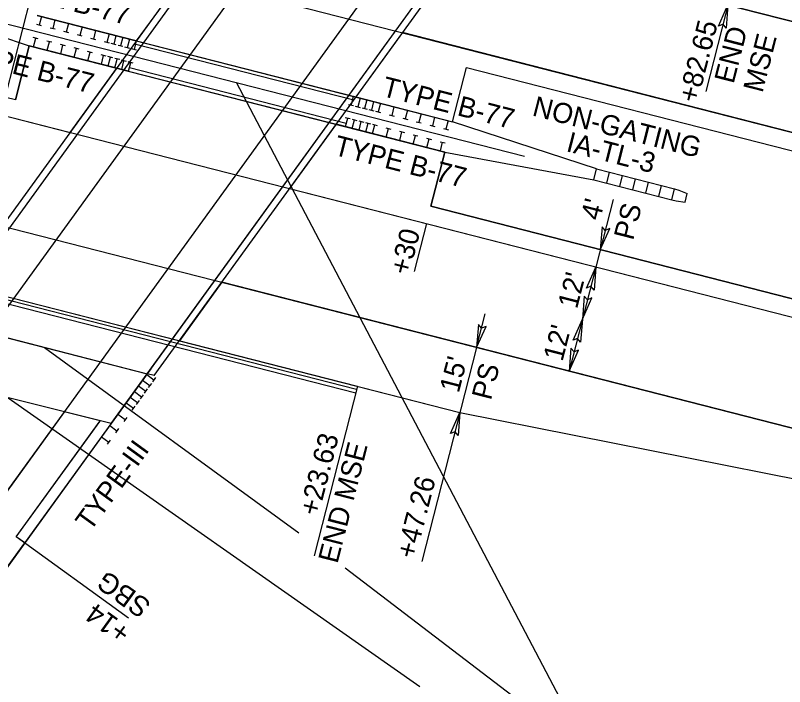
# Model space of a CAD drawing. Extents: x 1183930 to 1185370, y 573068 to 574871.
# Drawn here: x 1184495.2 to 1184666.9, y 573937.3 to 574087.2 of the extents above; entities that cross this region are included whole.
import ezdxf

# ---------------------------------------------------------------- set-up
doc = ezdxf.new("R2010")
doc.units = 0
for name, color, linetype in [('E_NCDOT_Terrain_Model_Flow_Arrows', 7, 'Continuous'), ('E_NCDOT_Terrain_Model_Spot_Elevation', 7, 'Continuous'), ('E_NCDOT_Terrain_Model_Triangles', 7, 'Continuous'), ('E_NCDOT_Vertical_Profile_Ground_Line', 7, 'Continuous'), ('P_NCDOT_Horizontal_Alignment', 7, 'Continuous'), ('P_NCDOT_Horizontal_Alignment_Curve_and_Spiral_Data', 7, 'Continuous'), ('P_NCDOT_Horizontal_Alignment_Direction_Label', 7, 'Continuous'), ('P_NCDOT_Horizontal_Alignment_Station_Label', 7, 'Continuous'), ('P_NCDOT_Horizontal_Alignment_Tick_Large', 7, 'Continuous'), ('P_NCDOT_Vertical_Profile_Grade', 7, 'Continuous'), ('P_RDY_Profile_Special_Ditch_L', 7, 'Continuous'), ('P_SMU_D_Unit_Label', 7, 'Continuous'), ('P_SMU_Deck', 7, 'Continuous'), ('PC_OBJECT', 7, 'Continuous'), ('PC_PADFOOTING', 7, 'Continuous'), ('PS_HATCH', 7, 'Continuous')]:
    doc.layers.add(name, color=color, linetype=linetype)

msp = doc.modelspace()

# ---------------------------------------------------------------- linework, layer by layer
for points in [[(1184652.15, 574084.85), (1184654.25, 574089.54), (1184653.86, 574084.38), (1184653.15, 574085.23)], [(1184626.14, 574040.02), (1184625.73, 574034.9), (1184627.87, 574039.61), (1184626.83, 574039.21)], [(1184622.64, 574026.34), (1184624.74, 574031.03), (1184624.35, 574025.87), (1184623.64, 574026.72)], [(1184622.18, 574024.52), (1184621.76, 574019.4), (1184623.9, 574024.11), (1184622.87, 574023.71)], [(1184619.66, 574014.72), (1184621.76, 574019.4), (1184621.37, 574014.25), (1184620.66, 574015.1)], [(1184598.55, 574018.19), (1184598.14, 574013.07), (1184600.28, 574017.77), (1184599.24, 574017.37)], [(1184619.2, 574012.9), (1184618.79, 574007.78), (1184620.92, 574012.49), (1184619.89, 574012.08)], [(1184592.32, 573993.85), (1184594.42, 573998.53), (1184594.03, 573993.38), (1184593.32, 573994.23)]]:
    msp.add_lwpolyline(points, close=True)
at = {"layer": 'E_NCDOT_Terrain_Model_Flow_Arrows'}
msp.add_line((1184432.84, 574038.35), (1184571.16, 574002.94), dxfattribs=at)
at = {"layer": 'E_NCDOT_Terrain_Model_Spot_Elevation'}
for p, q in [((1184522.09, 574080.79), (1184570.41, 574068.42)), ((1184569.05, 574063.09), (1184520.61, 574075.49)), ((1184571.34, 574003.67), (1184433.02, 574039.08))]:
    msp.add_line(p, q, dxfattribs=at)
at = {"layer": 'E_NCDOT_Terrain_Model_Triangles'}
for q in [(1184514.11, 573996.68), (1184514.01, 573996.54)]:
    msp.add_line((1184495.37, 573970.79), q, dxfattribs=at)
at = {"layer": 'E_NCDOT_Vertical_Profile_Ground_Line'}
for p, q in [((1184449.47, 573978.44), (1184665.23, 574276.54)), ((1184449.47, 573978.44), (1184665.23, 574276.54)), ((1184413.69, 573853.97), (1184639.53, 574165.99)), ((1184413.69, 573853.97), (1184639.53, 574165.99)), ((1184500, 574087.22), (1184592.76, 574063.47)), ((1184500, 574087.22), (1184592.76, 574063.47)), ((1184500, 574087.22), (1184592.76, 574063.47)), ((1184495.16, 574068.33), (1184498.26, 574080.44)), ((1184495.16, 574068.33), (1184498.26, 574080.44)), ((1184498.26, 574080.44), (1184591.02, 574056.69)), ((1184498.26, 574080.44), (1184591.02, 574056.69)), ((1184498.26, 574080.44), (1184591.02, 574056.69)), ((1184592.76, 574063.47), (1184595.86, 574075.58)), ((1184592.76, 574063.47), (1184595.86, 574075.58)), ((1184595.86, 574075.58), (1184964.43, 573981.23)), ((1184595.86, 574075.58), (1184964.43, 573981.23)), ((1184595.86, 574075.58), (1184970.78, 573979.6)), ((1184591.02, 574056.69), (1184587.92, 574044.58)), ((1184591.02, 574056.69), (1184587.92, 574044.58)), ((1184412.83, 574045.02), (1184569.95, 574004.8)), ((1184412.83, 574045.02), (1184594.42, 573998.53)), ((1184587.92, 574044.58), (1184956.49, 573950.23)), ((1184587.92, 574044.58), (1184956.49, 573950.23)), ((1184587.92, 574044.58), (1184962.85, 573948.6)), ((1184594.42, 573998.53), (1184790.9, 573959.59))]:
    msp.add_line(p, q, dxfattribs=at)
at = {"layer": 'P_NCDOT_Horizontal_Alignment'}
for p, q in [((1184397.22, 573889.19), (1184673.34, 574270.68)), ((1184405.59, 573859.83), (1184695.92, 574260.95)), ((1184143.08, 574220.4), (1184971.37, 574008.35)), ((1184143.08, 574220.4), (1184977.73, 574006.73)), ((1184137.13, 574197.15), (1184965.42, 573985.1)), ((1184137.13, 574197.15), (1184971.78, 573983.48)), ((1184127.21, 574158.4), (1184955.5, 573946.35)), ((1184127.21, 574158.4), (1184961.86, 573944.73)), ((1184121.26, 574135.15), (1184949.55, 573923.1)), ((1184121.26, 574135.15), (1184955.9, 573921.48))]:
    msp.add_line(p, q, dxfattribs=at)
at = {"layer": 'P_NCDOT_Horizontal_Alignment_Curve_and_Spiral_Data'}
for p, q in [((1184522.23, 574081.53), (1184570.6, 574069.15)), ((1184520.42, 574074.77), (1184568.86, 574062.37)), ((1184433.21, 574039.8), (1184571.53, 574004.39))]:
    msp.add_line(p, q, dxfattribs=at)
at = {"layer": 'P_NCDOT_Horizontal_Alignment_Direction_Label'}
for p, q in [((1184477.22, 574019.34), (1184562.83, 574137.61)), ((1184478.79, 574018.94), (1184564.39, 574137.21)), ((1184524.61, 574007.21), (1184610.21, 574125.48)), ((1184526.17, 574006.81), (1184611.78, 574125.08)), ((1184526.17, 574006.81), (1184524.61, 574007.21))]:
    msp.add_line(p, q, dxfattribs=at)
at = {"layer": 'P_NCDOT_Horizontal_Alignment_Station_Label'}
for p in [(1184478.79, 574018.94), (1184516.45, 573995.93), (1184516.55, 573996.08)]:
    msp.add_line(p, (1184524.61, 574007.21), dxfattribs=at)
msp.add_lwpolyline([(1184516.55, 573996.08), (1184470.52, 574007.53), (1184478.79, 574018.94), (1184524.61, 574007.21)], close=True, dxfattribs=at)
at = {"layer": 'P_NCDOT_Horizontal_Alignment_Tick_Large'}
for p, q in [((1184466.13, 574090.99), (1184498.26, 574080.44)), ((1184624.9, 574052.93), (1184592.76, 574063.47)), ((1184591.02, 574056.69), (1184624.28, 574050.5)), ((1184514.4, 573993.1), (1184413.69, 573853.97))]:
    msp.add_line(p, q, dxfattribs=at)
at = {"layer": 'P_NCDOT_Vertical_Profile_Grade'}
for p, q in [((1184522.16, 574081.55), (1184500, 574087.22)), ((1184500.97, 574086.97), (1184500.47, 574085.04)), ((1184504, 574086.2), (1184503.5, 574084.26)), ((1184501.03, 574084.89), (1184499.92, 574085.18)), ((1184504.05, 574084.12), (1184502.95, 574084.4)), ((1184507.02, 574085.42), (1184506.53, 574083.49)), ((1184510.05, 574084.65), (1184509.55, 574082.71)), ((1184513.08, 574083.87), (1184512.58, 574081.94)), ((1184500.28, 574081.99), (1184499.17, 574082.27)), ((1184499.23, 574080.19), (1184499.73, 574082.13)), ((1184507.08, 574083.34), (1184505.97, 574083.63)), ((1184510.11, 574082.57), (1184509, 574082.85)), ((1184513.14, 574081.79), (1184512.03, 574082.08)), ((1184516.11, 574083.1), (1184515.61, 574081.16)), ((1184517.62, 574082.71), (1184517.12, 574080.77)), ((1184519.13, 574082.32), (1184518.64, 574080.39)), ((1184520.42, 574074.77), (1184498.26, 574080.44)), ((1184503.31, 574081.21), (1184502.2, 574081.5)), ((1184502.26, 574079.42), (1184502.76, 574081.35)), ((1184506.34, 574080.44), (1184505.23, 574080.72)), ((1184505.29, 574078.64), (1184505.78, 574080.58)), ((1184516.16, 574081.02), (1184515.05, 574081.3)), ((1184517.68, 574080.63), (1184516.57, 574080.92)), ((1184519.19, 574080.24), (1184518.08, 574080.53)), ((1184520.65, 574081.94), (1184520.15, 574080)), ((1184522.16, 574081.55), (1184521.66, 574079.61)), ((1184509.37, 574079.66), (1184508.26, 574079.95)), ((1184508.31, 574077.87), (1184508.81, 574079.8)), ((1184512.39, 574078.89), (1184511.28, 574079.17)), ((1184511.34, 574077.09), (1184511.84, 574079.03)), ((1184520.71, 574079.86), (1184519.6, 574080.14)), ((1184522.22, 574079.47), (1184521.11, 574079.75)), ((1184515.42, 574078.11), (1184514.31, 574078.4)), ((1184514.37, 574076.32), (1184514.87, 574078.25)), ((1184516.93, 574077.72), (1184515.82, 574078.01)), ((1184515.88, 574075.93), (1184516.38, 574077.87)), ((1184518.45, 574077.34), (1184517.34, 574077.62)), ((1184517.4, 574075.54), (1184517.89, 574077.48)), ((1184519.96, 574076.95), (1184518.85, 574077.23)), ((1184518.91, 574075.15), (1184519.41, 574077.09)), ((1184521.48, 574076.56), (1184520.37, 574076.85)), ((1184520.42, 574074.77), (1184520.92, 574076.7)), ((1184570.6, 574069.15), (1184570.1, 574067.21)), ((1184570.6, 574069.15), (1184592.76, 574063.47)), ((1184572.11, 574068.76), (1184571.62, 574066.82)), ((1184573.63, 574068.37), (1184573.13, 574066.44)), ((1184569.55, 574067.35), (1184570.66, 574067.07)), ((1184571.06, 574066.97), (1184572.17, 574066.68)), ((1184572.57, 574066.58), (1184573.68, 574066.29)), ((1184575.14, 574067.99), (1184574.64, 574066.05)), ((1184576.65, 574067.6), (1184576.16, 574065.66)), ((1184579.68, 574066.82), (1184579.18, 574064.89)), ((1184574.09, 574066.19), (1184575.2, 574065.91)), ((1184575.6, 574065.8), (1184576.71, 574065.52)), ((1184578.63, 574065.03), (1184579.74, 574064.74)), ((1184582.71, 574066.05), (1184582.21, 574064.11)), ((1184585.73, 574065.27), (1184585.24, 574063.34)), ((1184568.8, 574064.45), (1184569.91, 574064.16)), ((1184568.86, 574062.37), (1184569.36, 574064.3)), ((1184570.32, 574064.06), (1184571.43, 574063.77)), ((1184570.38, 574061.98), (1184570.87, 574063.92)), ((1184571.83, 574063.67), (1184572.94, 574063.39)), ((1184571.89, 574061.59), (1184572.39, 574063.53)), ((1184573.34, 574063.28), (1184574.45, 574063)), ((1184573.4, 574061.2), (1184573.9, 574063.14)), ((1184581.66, 574064.25), (1184582.77, 574063.97)), ((1184584.68, 574063.48), (1184585.79, 574063.19)), ((1184588.76, 574064.5), (1184588.27, 574062.56)), ((1184591.79, 574063.72), (1184591.29, 574061.79)), ((1184568.86, 574062.37), (1184591.02, 574056.69)), ((1184574.86, 574062.9), (1184575.97, 574062.61)), ((1184574.92, 574060.82), (1184575.41, 574062.75)), ((1184577.89, 574062.12), (1184579, 574061.84)), ((1184577.94, 574060.04), (1184578.44, 574061.98)), ((1184587.71, 574062.7), (1184588.82, 574062.42)), ((1184590.74, 574061.93), (1184591.85, 574061.64)), ((1184580.91, 574061.35), (1184582.02, 574061.06)), ((1184580.97, 574059.27), (1184581.47, 574061.2)), ((1184583.94, 574060.57), (1184585.05, 574060.29)), ((1184584, 574058.49), (1184584.49, 574060.43)), ((1184586.97, 574059.8), (1184588.08, 574059.51)), ((1184587.03, 574057.72), (1184587.52, 574059.65)), ((1184589.99, 574059.02), (1184591.1, 574058.74)), ((1184590.05, 574056.94), (1184590.55, 574058.88)), ((1184525.39, 574008.29), (1184514.4, 573993.1)), ((1184524.48, 574007.03), (1184526.1, 574005.85)), ((1184523.56, 574005.76), (1184525.18, 574004.59)), ((1184525.52, 574005.05), (1184524.84, 574004.12)), ((1184526.43, 574006.32), (1184525.76, 574005.39)), ((1184521.73, 574003.23), (1184523.35, 574002.06)), ((1184522.64, 574004.49), (1184524.26, 574003.32)), ((1184524.6, 574003.79), (1184523.93, 574002.86)), ((1184520.81, 574001.96), (1184522.43, 574000.79)), ((1184523.68, 574002.52), (1184523.01, 574001.59)), ((1184519.9, 574000.7), (1184521.52, 573999.52)), ((1184521.85, 573999.99), (1184521.18, 573999.06)), ((1184522.77, 574001.25), (1184522.1, 574000.33)), ((1184518.06, 573998.17), (1184519.68, 573996.99)), ((1184520.02, 573997.46), (1184519.35, 573996.53)), ((1184516.23, 573995.63), (1184517.85, 573994.46)), ((1184518.19, 573994.93), (1184517.52, 573994)), ((1184514.4, 573993.1), (1184516.02, 573991.93)), ((1184516.35, 573992.39), (1184515.68, 573991.47))]:
    msp.add_line(p, q, dxfattribs=at)
at = {"layer": 'P_RDY_Profile_Special_Ditch_L'}
for p, q in [((1184624.28, 574050.5), (1184624.9, 574052.93)), ((1184624.9, 574052.93), (1184627.8, 574052.18)), ((1184627.18, 574049.76), (1184627.8, 574052.18)), ((1184627.8, 574052.18), (1184630.71, 574051.44)), ((1184630.09, 574049.02), (1184630.71, 574051.44)), ((1184630.71, 574051.44), (1184633.61, 574050.69)), ((1184624.28, 574050.5), (1184627.18, 574049.76)), ((1184627.18, 574049.76), (1184630.09, 574049.02)), ((1184632.99, 574048.27), (1184633.61, 574050.69)), ((1184633.61, 574050.69), (1184636.52, 574049.95)), ((1184635.9, 574047.53), (1184636.52, 574049.95)), ((1184636.52, 574049.95), (1184639.43, 574049.2)), ((1184630.09, 574049.02), (1184632.99, 574048.27)), ((1184632.99, 574048.27), (1184635.9, 574047.53)), ((1184638.81, 574046.78), (1184639.43, 574049.2)), ((1184639.43, 574049.2), (1184642.33, 574048.46)), ((1184641.71, 574046.04), (1184642.33, 574048.46)), ((1184642.33, 574048.46), (1184643.3, 574048.21)), ((1184643.3, 574048.21), (1184645.18, 574047.47)), ((1184635.9, 574047.53), (1184638.81, 574046.78)), ((1184638.81, 574046.78), (1184641.71, 574046.04)), ((1184641.71, 574046.04), (1184642.68, 574045.79)), ((1184644.68, 574045.54), (1184644.93, 574046.51)), ((1184644.93, 574046.51), (1184645.18, 574047.47)), ((1184642.68, 574045.79), (1184644.68, 574045.54))]:
    msp.add_line(p, q, dxfattribs=at)
at = {"layer": 'P_SMU_D_Unit_Label'}
msp.add_line((1184424.65, 574102.9), (1184608.83, 574055.75), dxfattribs=at)
at = {"layer": 'P_SMU_Deck'}
msp.add_line((1184487.54, 574047.99), (1184511.87, 574143.02), dxfattribs=at)
at = {"layer": 'PC_OBJECT'}
for p, q in [((1184495.16, 574068.33), (1184128.2, 574162.27)), ((1184127.21, 574158.4), (1184507.42, 574061.06)), ((1184977.73, 574006.73), (1184596.71, 574104.27)), ((1184522.23, 574081.53), (1184532.63, 574095.9)), ((1184500, 574087.22), (1184500.97, 574086.97)), ((1184507.02, 574085.42), (1184510.05, 574084.65)), ((1184510.05, 574084.65), (1184513.08, 574083.87)), ((1184513.08, 574083.87), (1184516.11, 574083.1)), ((1184581.58, 574083.37), (1184571.18, 574069)), ((1184965.42, 573985.1), (1184581.58, 574083.37)), ((1184498.26, 574080.44), (1184495.16, 574068.33)), ((1184517.82, 574075.43), (1184498.26, 574080.44)), ((1184522.16, 574081.55), (1184522.23, 574081.53)), ((1184507.42, 574061.06), (1184517.82, 574075.43)), ((1184592.76, 574063.47), (1184595.86, 574075.58)), ((1184595.86, 574075.58), (1184964.43, 573981.23)), ((1184571.18, 574069), (1184592.76, 574063.47)), ((1184566.77, 574062.9), (1184556.37, 574048.53)), ((1184591.02, 574056.69), (1184566.77, 574062.9)), ((1184587.92, 574044.58), (1184591.02, 574056.69)), ((1184556.37, 574048.53), (1184955.5, 573946.35)), ((1184956.49, 573950.23), (1184587.92, 574044.58)), ((1184541.24, 574027.63), (1184531.79, 574014.57)), ((1184949.55, 573923.1), (1184541.24, 574027.63)), ((1184531.79, 574014.57), (1184594.42, 573998.53)), ((1184505.98, 573998.53), (1184405.59, 573859.83)), ((1184594.42, 573998.53), (1184790.9, 573959.59))]:
    msp.add_line(p, q, dxfattribs=at)
for points in [[(1184500.97, 574086.97), (1184504, 574086.2), (1184507.02, 574085.42)], [(1184516.11, 574083.1), (1184517.62, 574082.71), (1184519.13, 574082.32), (1184520.65, 574081.94), (1184522.16, 574081.55)], [(1184514.01, 573996.54), (1184514.11, 573996.68), (1184506.09, 573998.68), (1184505.98, 573998.53)], [(1184413.69, 573853.97), (1184497.26, 573969.42), (1184495.37, 573970.79), (1184514.01, 573996.54)]]:
    msp.add_lwpolyline(points, dxfattribs=at)
at = {"layer": 'PC_PADFOOTING'}
for p, q in [((1184658, 574104.2), (1184649.3, 574070.22)), ((1184628.6, 574046.11), (1184618.79, 574007.78)), ((1184586.93, 574040.71), (1184584.2, 574030.04)), ((1184598.14, 574013.07), (1184600.07, 574020.6)), ((1184598.14, 574013.07), (1184585.9, 573965.26)), ((1184571.53, 574004.39), (1184561.84, 573966.54)), ((1184520.45, 573952.63), (1184495.37, 573970.79))]:
    msp.add_line(p, q, dxfattribs=at)
at = {"layer": 'PS_HATCH'}
for p, q in [((1184635.16, 573899.7), (1184544.5, 574072.22)), ((1184501.7, 574013.08), (1184558.46, 573971.68)), ((1184493.54, 574001.8), (1184585.45, 573937.33)), ((1184594.42, 573998.53), (1184790.9, 573959.59)), ((1184568.79, 573963.84), (1184613.51, 573929.74))]:
    msp.add_line(p, q, dxfattribs=at)

# ---------------------------------------------------------------- texts
at = {"layer": 'PC_PADFOOTING'}
for s, rotation, p in [('+82.65', 75.6405, (1184647.42, 574067.45)), ('END', 75.6405, (1184655.5, 574071.78)), ('MSE', 75.6405, (1184661.95, 574069.77)), ("4'", 75.6405, (1184625.66, 574041.22)), ('PS', 75.6405, (1184633.07, 574036.81)), ('+30', 75.6405, (1184583.05, 574029.02)), ("12'", 75.6405, (1184620.55, 574021.51)), ("12'", 75.6405, (1184617.3, 574009.77)), ("15'", 75.6405, (1184594.15, 574002.73)), ('PS', 75.6405, (1184601.33, 574001.1)), ('+23.63', 75.6405, (1184562.8, 573975.22)), ('END MSE', 75.6405, (1184567.06, 573964.63)), ('+47.26', 75.6405, (1184584.43, 573965.64)), ('SBG', 144.103, (1184525.75, 573955.99)), ('+14', 144.103, (1184521.28, 573950.2))]:
    msp.add_text(s, height=4.5, rotation=rotation, dxfattribs=at).set_placement(p)
at = {"layer": 'PS_HATCH'}
for s, rotation, p in [('TYPE B-77', 345.6405, (1184490.98, 574092.48)), ('TYPE B-77', 345.6405, (1184482.85, 574077.2)), ('TYPE B-77', 345.6405, (1184576.75, 574069.27)), ('NON-GATING', 345.6405, (1184610.35, 574064.91)), ('TYPE B-77', 345.6405, (1184566.01, 574056.15)), ('IA-TL-3', 345.6405, (1184617.93, 574056.93)), ('TYPE-III', 54.0376, (1184511.9, 573971.82))]:
    msp.add_text(s, height=4.5, rotation=rotation, dxfattribs=at).set_placement(p)

doc.saveas('drawing.dxf')
